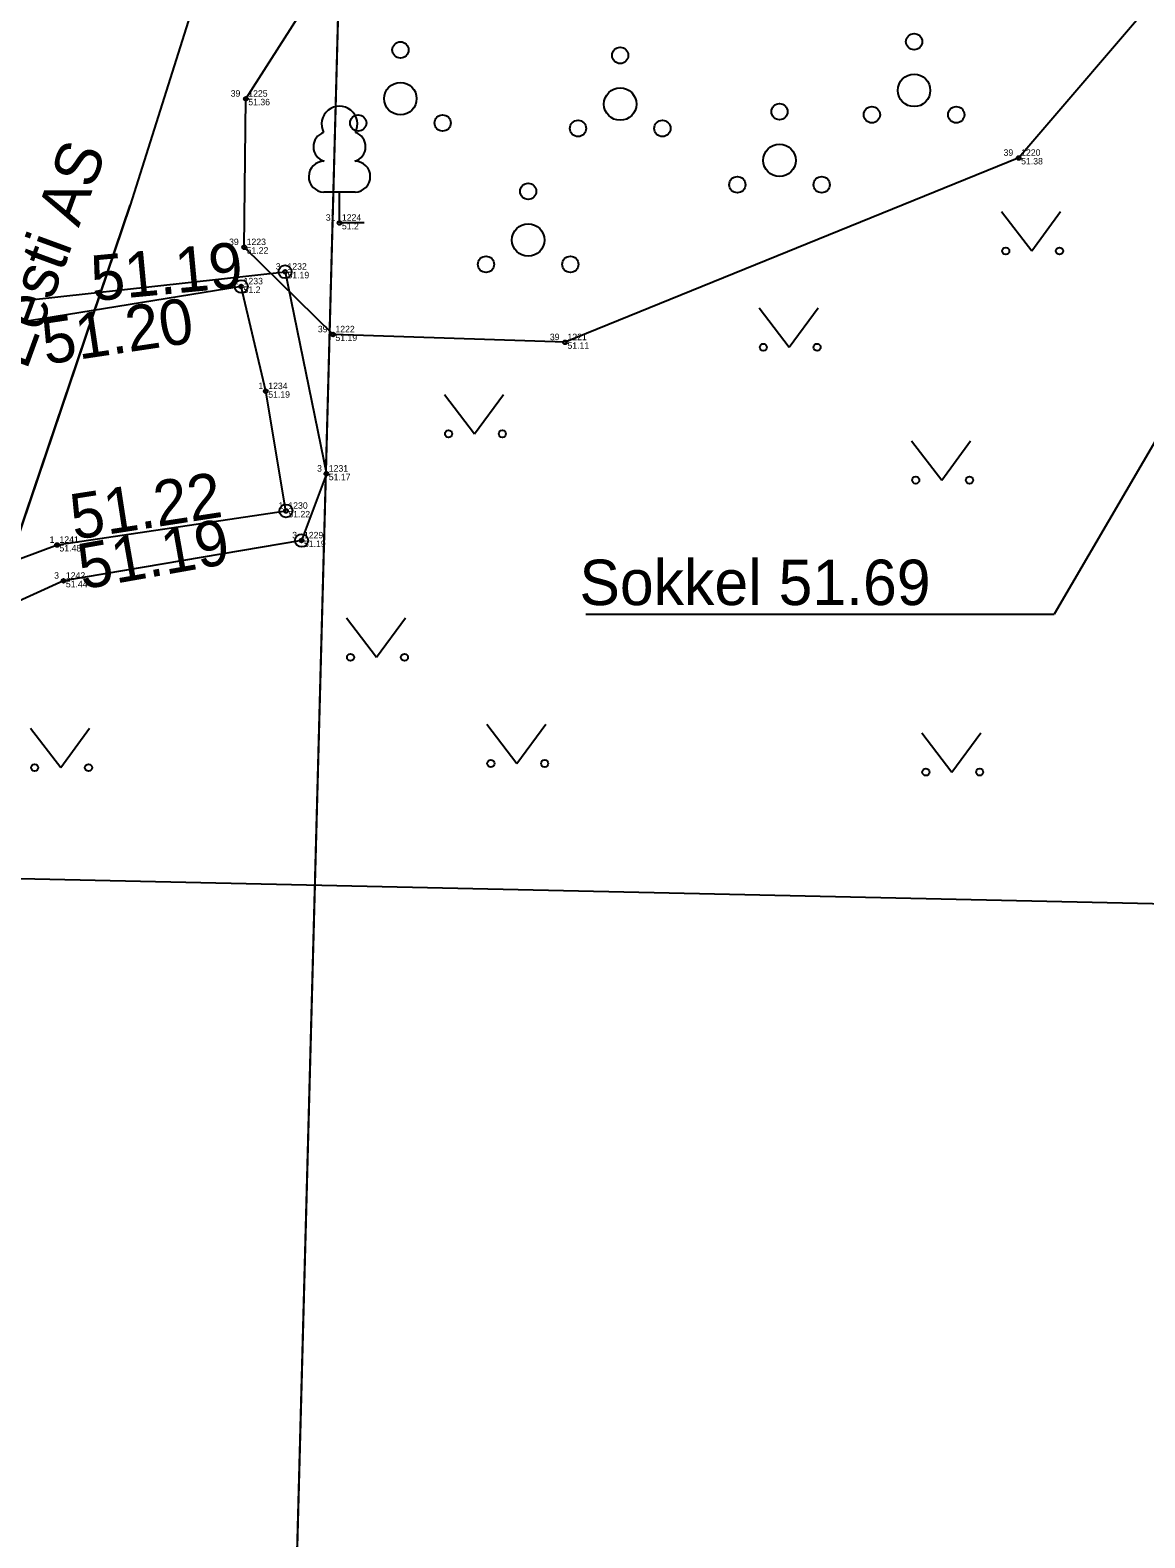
# Model space of a CAD drawing. Extents: x 543497 to 552146, y 6567125 to 6579845.
# Drawn here: x 546568.77 to 546585.95, y 6577746.86 to 6577770.08 of the extents above; entities that cross this region are included whole.
import ezdxf

# ---------------------------------------------------------------- set-up
doc = ezdxf.new("R2010")
doc.units = 0
for name, color, linetype in [('xref_Kangru tee 1_geodeesia$0$HALJASTUS', 7, 'Continuous'), ('xref_Kangru tee 1_geodeesia$0$HOONEDET', 7, 'Continuous'), ('xref_Kangru tee 1_geodeesia$0$korgus-EH2000', 7, 'Continuous'), ('xref_Kangru tee 1_geodeesia$0$mootkood', 7, 'Continuous'), ('xref_Kangru tee 1_geodeesia$0$MOOTKORG-eh2000', 7, 'Continuous'), ('xref_Kangru tee 1_geodeesia$0$mootmpunkt', 7, 'Continuous'), ('xref_Kangru tee 1_geodeesia$0$MOOTNR', 7, 'Continuous'), ('xref_Kangru tee 1_geodeesia$0$MOOTPIIR', 7, 'Continuous'), ('xref_Kangru tee 1_geodeesia$0$PIIR', 7, 'Continuous'), ('xref_Kangru tee 1_geodeesia$0$PUU', 7, 'Continuous'), ('xref_Kangru tee 1_geodeesia$0$SITRASS', 7, 'Continuous'), ('xref_Kangru tee 1_geodeesia$0$TEE', 7, 'Continuous')]:
    doc.layers.add(name, color=color, linetype=linetype)

# ---------------------------------------------------------------- blocks, each defined once
blk = doc.blocks.new('xref_Kangru tee 1_geodeesia$0$LEHTP1')
for p, q in [((0.48, 0.95), (-0.48, 0.95)), ((0, 0), (0, 0.95)), ((0.76, 0), (0, 0))]:
    blk.add_line(p, q)
for centre, radius, start, end in [((0, 3.04), 0.554, 332.5799, 207.4201), ((-0.34, 2.345), 0.465, 109.0217, 253.1415), ((0.34, 2.345), 0.465, 286.8508, 70.9859), ((-0.475, 1.425), 0.475, 90.0016, 269.3953), ((0.475, 1.425), 0.475, 270.6047, 89.9984)]:
    blk.add_arc(centre, radius, start, end)
blk = doc.blocks.new('xref_Kangru tee 1_geodeesia$0$PQQSAS')
for centre, radius in [((0, 1.5), 0.25), ((0, 0), 0.5), ((-1.3, -0.75), 0.25), ((1.3, -0.75), 0.25)]:
    blk.add_circle(centre, radius)
blk = doc.blocks.new('xref_Kangru tee 1_geodeesia$0$MURU')
for p, q in [((-0.927, 1.213), (0, 0)), ((0, 0), (0.891, 1.213))]:
    blk.add_line(p, q)
for centre in [(-0.802, 0), (0.856, 0)]:
    blk.add_circle(centre, 0.11)

msp = doc.modelspace()

# ---------------------------------------------------------------- linework, layer by layer
at = {"layer": 'xref_Kangru tee 1_geodeesia$0$HALJASTUS'}
msp.add_lwpolyline([(546584.111, 6577772.806), (546586.252, 6577770.743), (546584.008, 6577768.116), (546577.016, 6577765.276), (546573.44, 6577765.397), (546572.072, 6577766.741), (546572.097, 6577769.027), (546574.299, 6577772.475), (546584.111, 6577772.806)], dxfattribs=at)
at = {"layer": 'xref_Kangru tee 1_geodeesia$0$HOONEDET'}
for points in [[(546586.765, 6577764.867), (546584.554, 6577761.088)], [(546577.337, 6577761.088), (546584.554, 6577761.088)]]:
    msp.add_lwpolyline(points, dxfattribs=at)
at = {"layer": 'xref_Kangru tee 1_geodeesia$0$korgus-EH2000'}
for centre in [(546572.701, 6577766.362), (546572.025, 6577766.136), (546572.715, 6577762.679), (546572.955, 6577762.223)]:
    msp.add_circle(centre, 0.1, dxfattribs=at)
at = {"layer": 'xref_Kangru tee 1_geodeesia$0$mootmpunkt'}
for centre in [(546572.097, 6577769.027), (546584.008, 6577768.116), (546573.54, 6577767.116), (546572.072, 6577766.741), (546572.701, 6577766.362), (546572.025, 6577766.136), (546573.44, 6577765.397), (546577.016, 6577765.276), (546572.405, 6577764.522), (546573.338, 6577763.251), (546572.715, 6577762.679), (546569.187, 6577762.154), (546572.955, 6577762.223), (546569.286, 6577761.602)]:
    msp.add_circle(centre, 0.03, dxfattribs=at)
at = {"layer": 'xref_Kangru tee 1_geodeesia$0$MOOTPIIR'}
msp.add_lwpolyline([(546561.855, 6577757.167), (546592.359, 6577756.495), (546598.215, 6577760.492), (546601.677, 6577762.542), (546610.627, 6577767.104), (546615.752, 6577767.43), (546620.643, 6577768.598)], dxfattribs=at)
at = {"layer": 'xref_Kangru tee 1_geodeesia$0$PIIR'}
for points in [[(546741.41, 6577111.25), (546683.61, 6577317.78), (546673.81, 6577353.39), (546663.96, 6577389.17), (546660.51, 6577401.7), (546647.19, 6577450.09), (546634.65, 6577495.62), (546625.43, 6577526.07), (546609.43, 6577571.52), (546593.21, 6577617.62), (546579.42, 6577656.79), (546562.86, 6577702.03), (546544.17, 6577758.03), (546521.59, 6577770.69), (546573.78, 6577780.87), (546573.57, 6577772.24), (546572.44, 6577729.89), (546568.55, 6577727.96), (546603, 6577632.08), (546611.62, 6577607.53), (546638.72, 6577530.39), (546648.14, 6577499.5), (546658.9, 6577460.58), (546749.51, 6577130.19)], [(546572.44, 6577729.89), (546573.57, 6577772.24), (546613.94, 6577777.23), (546617.58, 6577769.56), (546644.8, 6577768), (546649.32, 6577758.15), (546629.37, 6577744.28), (546606.33, 6577728.26), (546597.82, 6577742.14), (546572.44, 6577729.89)]]:
    msp.add_lwpolyline(points, dxfattribs=at)
at = {"layer": 'xref_Kangru tee 1_geodeesia$0$SITRASS'}
msp.add_line((546567.217, 6577758.248), (546570.312, 6577767.388), dxfattribs=at)
msp.add_lwpolyline([(546573.919, 6577773.607), (546572.16, 6577773.249), (546571.76, 6577771.98), (546570.312, 6577767.388), (546567.217, 6577758.248), (546566.268, 6577755.637), (546566.058, 6577755.169)], dxfattribs=at)
at = {"layer": 'xref_Kangru tee 1_geodeesia$0$TEE'}
for points in [[(546549.683, 6577756.576), (546553.201, 6577759.509), (546558.42, 6577760.898), (546562.772, 6577763.848), (546565.862, 6577765.249), (546567.186, 6577765.756), (546572.701, 6577766.362), (546573.338, 6577763.251), (546572.955, 6577762.223), (546569.286, 6577761.602), (546566.453, 6577760.312), (546564.257, 6577758.907), (546561.855, 6577757.167)], [(546561.477, 6577757.328), (546563.852, 6577759.682), (546565.891, 6577760.929), (546569.187, 6577762.154), (546572.715, 6577762.679), (546572.405, 6577764.522), (546572.025, 6577766.136), (546568.188, 6577765.517), (546566.1, 6577764.934), (546562.894, 6577763.361), (546558.715, 6577760.537), (546553.273, 6577758.859), (546549.683, 6577756.576), (546549.581, 6577755.854)]]:
    msp.add_lwpolyline(points, dxfattribs=at)

# ---------------------------------------------------------------- block references
at = {"layer": 'xref_Kangru tee 1_geodeesia$0$HALJASTUS', "xscale": 0.5, "yscale": 0.5}
for name, p in [('xref_Kangru tee 1_geodeesia$0$PQQSAS', (546582.395, 6577769.157)), ('xref_Kangru tee 1_geodeesia$0$PQQSAS', (546574.479, 6577769.03)), ('xref_Kangru tee 1_geodeesia$0$PQQSAS', (546577.866, 6577768.946)), ('xref_Kangru tee 1_geodeesia$0$PQQSAS', (546580.321, 6577768.079)), ('xref_Kangru tee 1_geodeesia$0$PQQSAS', (546576.448, 6577766.852)), ('xref_Kangru tee 1_geodeesia$0$MURU', (546584.208, 6577766.683)), ('xref_Kangru tee 1_geodeesia$0$MURU', (546580.472, 6577765.2)), ('xref_Kangru tee 1_geodeesia$0$MURU', (546575.622, 6577763.866)), ('xref_Kangru tee 1_geodeesia$0$MURU', (546582.821, 6577763.153)), ('xref_Kangru tee 1_geodeesia$0$MURU', (546574.112, 6577760.424)), ('xref_Kangru tee 1_geodeesia$0$MURU', (546569.243, 6577758.724)), ('xref_Kangru tee 1_geodeesia$0$MURU', (546576.274, 6577758.788)), ('xref_Kangru tee 1_geodeesia$0$MURU', (546582.978, 6577758.656))]:
    msp.add_blockref(name, p, dxfattribs=at)
at = {"layer": 'xref_Kangru tee 1_geodeesia$0$PUU', "xscale": 0.5, "yscale": 0.5}
msp.add_blockref('xref_Kangru tee 1_geodeesia$0$LEHTP1', (546573.54, 6577767.116), dxfattribs=at)

# ---------------------------------------------------------------- texts
at = {"layer": 'xref_Kangru tee 1_geodeesia$0$HOONEDET'}
msp.add_text('Sokkel 51.69', height=0.7, dxfattribs=at).set_placement((546577.237, 6577761.228))
at = {"layer": 'xref_Kangru tee 1_geodeesia$0$korgus-EH2000'}
for s, rotation, p in [(' 51.19 ', 5.3915, (546569.483, 6577765.885)), (' 51.20 ', 8.5109, (546568.751, 6577764.894)), (' 51.22 ', 8.794, (546569.191, 6577762.194)), (' 51.19 ', 10.0743, (546569.322, 6577761.422))]:
    msp.add_text(s, height=0.7, rotation=rotation, dxfattribs=at).set_placement(p)
at = {"layer": 'xref_Kangru tee 1_geodeesia$0$mootkood'}
for s, p in [(' 39', (546571.826, 6577769.06)), (' 39', (546583.737, 6577768.149)), (' 31', (546573.292, 6577767.149)), (' 39', (546571.801, 6577766.774)), (' 3', (546572.52, 6577766.395)), (' 1', (546571.873, 6577766.169)), (' 39', (546573.169, 6577765.43)), (' 39', (546576.745, 6577765.309)), (' 1', (546572.253, 6577764.555)), (' 3', (546573.157, 6577763.284)), (' 1', (546572.563, 6577762.712)), (' 3', (546572.774, 6577762.256)), (' 1', (546569.035, 6577762.187)), (' 3', (546569.105, 6577761.635))]:
    msp.add_text(s, height=0.1, dxfattribs=at).set_placement(p)
at = {"layer": 'xref_Kangru tee 1_geodeesia$0$MOOTKORG-eh2000'}
for s, p in [(' 51.36', (546572.097, 6577768.927)), (' 51.38', (546584.008, 6577768.016)), (' 51.2', (546573.54, 6577767.016)), (' 51.22', (546572.072, 6577766.641)), (' 51.19', (546572.701, 6577766.262)), (' 51.2', (546572.025, 6577766.036)), (' 51.19', (546573.44, 6577765.297)), (' 51.11', (546577.016, 6577765.176)), (' 51.19', (546572.405, 6577764.422)), (' 51.17', (546573.338, 6577763.151)), (' 51.22', (546572.715, 6577762.579)), (' 51.48', (546569.187, 6577762.054)), (' 51.19', (546572.955, 6577762.123)), (' 51.44', (546569.286, 6577761.502))]:
    msp.add_text(s, height=0.1, dxfattribs=at).set_placement(p)
at = {"layer": 'xref_Kangru tee 1_geodeesia$0$MOOTNR'}
for s, p in [(' 1225', (546572.097, 6577769.06)), (' 1220', (546584.008, 6577768.149)), (' 1224', (546573.54, 6577767.149)), (' 1223', (546572.072, 6577766.774)), (' 1232', (546572.701, 6577766.395)), (' 1233', (546572.025, 6577766.169)), (' 1222', (546573.44, 6577765.43)), (' 1221', (546577.016, 6577765.309)), (' 1234', (546572.405, 6577764.555)), (' 1231', (546573.338, 6577763.284)), (' 1230', (546572.715, 6577762.712)), (' 1229', (546572.955, 6577762.256)), (' 1241', (546569.187, 6577762.187)), (' 1242', (546569.286, 6577761.635))]:
    msp.add_text(s, height=0.1, dxfattribs=at).set_placement(p)
at = {"layer": 'xref_Kangru tee 1_geodeesia$0$SITRASS'}
msp.add_text('Telia Eesti AS', height=0.7, rotation=69.9337, dxfattribs=at).set_placement((546567.932, 6577762.684))

doc.saveas('drawing.dxf')
